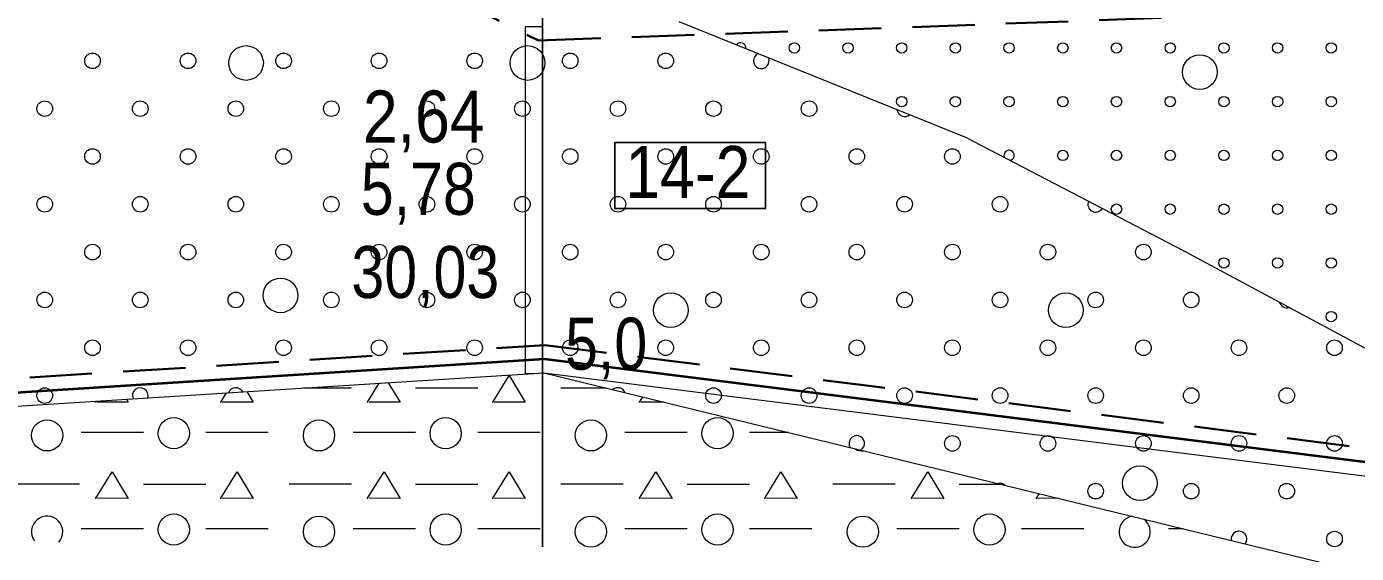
# Model space of a CAD drawing. Extents: x 640104 to 640970, y 6442278 to 6442689.
# Drawn here: x 640620 to 640696.8, y 6442553.6 to 6442583.9 of the extents above; entities that cross this region are included whole.
import ezdxf
from ezdxf.enums import TextEntityAlignment as Align

# ---------------------------------------------------------------- set-up
doc = ezdxf.new("R2010")
doc.units = 0
doc.header["$LTSCALE"] = 1.2
doc.linetypes.add('MEDIUM_DASHED', pattern=[4.5, 3, -1.5])
for name, color, linetype, lineweight in [('31', 7, 'Continuous', 13), ('32', 7, 'Continuous', 25), ('33', 7, 'Continuous', 13), ('35', 7, 'Continuous', 35), ('42', 7, 'Continuous', 13), ('43', 7, 'Continuous', 13), ('46', 7, 'Continuous', 13), ('47', 7, 'Continuous', 13)]:
    doc.layers.add(name, color=color, linetype=linetype, lineweight=lineweight)

msp = doc.modelspace()

# ---------------------------------------------------------------- linework, layer by layer
at = {"layer": '31'}
for points in [[(640657.64, 6442584.24), (640674.2, 6442577.56), (640686.8, 6442571.01), (640698.09, 6442564.96), (640704.51, 6442561.06), (640714.77, 6442554.82), (640726.06, 6442549.09), (640743.8, 6442541.09)], [(640553.71, 6442558.56), (640570.07, 6442558.94), (640649.85, 6442563.98), (640763.79, 6442536.22), (640808.67, 6442524.48), (640822.17, 6442520.94), (640837.77, 6442517.67), (640873.2, 6442509.45), (640884.27, 6442508.94), (640895.27, 6442508.94), (640947.47, 6442510.44), (640955.05, 6442510.44)]]:
    msp.add_lwpolyline(points, dxfattribs=at)
at = {"layer": '32'}
msp.add_line((640649.77, 6442613.94), (640649.77, 6442553.94), dxfattribs=at)
at = {"layer": '33'}
msp.add_lwpolyline([(640648.77, 6442583.94), (640648.77, 6442563.94), (640649.27, 6442563.94), (640649.77, 6442563.97), (640649.77, 6442563.98), (640649.77, 6442583.94), (640649.72, 6442583.94)], close=True, dxfattribs=at)
at = {"layer": '33', "lineweight": 25}
msp.add_lwpolyline([(640653.94, 6442577.26), (640662.65, 6442577.26), (640662.65, 6442573.46), (640653.94, 6442573.46)], close=True, dxfattribs=at)
at = {"layer": '35', "linetype": 'MEDIUM_DASHED'}
msp.add_line((640571.67, 6442560.65), (640649.9, 6442565.58), dxfattribs=at)
at = {"layer": '35', "lineweight": 40}
msp.add_line((640570.87, 6442559.79), (640649.88, 6442564.78), dxfattribs=at)
at = {"layer": '35', "linetype": 'MEDIUM_DASHED'}
for points in [[(640571.67, 6442622.27), (640649.54, 6442583.14), (640758.17, 6442587.08)], [(640649.9, 6442565.58), (640761.11, 6442551.63), (640823.77, 6442547.45)]]:
    msp.add_lwpolyline(points, dxfattribs=at)
at = {"layer": '35', "lineweight": 40}
msp.add_lwpolyline([(640649.88, 6442564.78), (640761.03, 6442550.84), (640822.97, 6442546.7)], dxfattribs=at)
at = {"layer": '35', "lineweight": 13}
msp.add_lwpolyline([(640649.85, 6442563.98), (640760.96, 6442550.04), (640822.17, 6442545.95)], dxfattribs=at)
at = {"layer": '42'}
for centre in [(640623.796, 6442581.971), (640629.311, 6442581.971), (640634.827, 6442581.971), (640640.342, 6442581.971), (640645.858, 6442581.971), (640651.373, 6442581.971), (640656.888, 6442581.971), (640621.038, 6442579.213), (640626.553, 6442579.213), (640632.069, 6442579.213), (640637.584, 6442579.213), (640643.1, 6442579.213), (640648.615, 6442579.213), (640654.131, 6442579.213), (640659.646, 6442579.213), (640665.162, 6442579.213), (640623.796, 6442576.456), (640629.311, 6442576.456), (640634.827, 6442576.456), (640640.342, 6442576.456), (640645.858, 6442576.456), (640651.373, 6442576.456), (640656.888, 6442576.456), (640662.404, 6442576.456), (640667.919, 6442576.456), (640673.435, 6442576.456), (640621.038, 6442573.698), (640626.553, 6442573.698), (640632.069, 6442573.698), (640637.584, 6442573.698), (640643.1, 6442573.698), (640648.615, 6442573.698), (640654.131, 6442573.698), (640659.646, 6442573.698), (640665.162, 6442573.698), (640670.677, 6442573.698), (640676.192, 6442573.698), (640623.796, 6442570.94), (640629.311, 6442570.94), (640634.827, 6442570.94), (640640.342, 6442570.94), (640645.858, 6442570.94), (640651.373, 6442570.94), (640656.888, 6442570.94), (640662.404, 6442570.94), (640667.919, 6442570.94), (640673.435, 6442570.94), (640678.95, 6442570.94), (640684.466, 6442570.94), (640621.038, 6442568.182), (640626.553, 6442568.182), (640632.069, 6442568.182), (640637.584, 6442568.182), (640643.1, 6442568.182), (640648.615, 6442568.182), (640654.131, 6442568.182), (640659.646, 6442568.182), (640665.162, 6442568.182), (640670.677, 6442568.182), (640676.192, 6442568.182), (640681.708, 6442568.182), (640687.223, 6442568.182), (640623.796, 6442565.425), (640629.311, 6442565.425), (640634.827, 6442565.425), (640640.342, 6442565.425), (640645.858, 6442565.425), (640651.373, 6442565.425), (640656.888, 6442565.425), (640662.404, 6442565.425), (640667.919, 6442565.425), (640673.435, 6442565.425), (640678.95, 6442565.425), (640684.466, 6442565.425), (640689.981, 6442565.425), (640695.496, 6442565.425), (640621.038, 6442562.667), (640659.646, 6442562.667), (640665.162, 6442562.667), (640670.677, 6442562.667), (640676.192, 6442562.667), (640681.708, 6442562.667), (640687.223, 6442562.667), (640692.739, 6442562.667), (640673.435, 6442559.909), (640678.95, 6442559.909), (640684.466, 6442559.909), (640689.981, 6442559.909), (640695.496, 6442559.909), (640681.708, 6442557.152), (640687.223, 6442557.152), (640692.739, 6442557.152), (640695.496, 6442554.394)]:
    msp.add_circle(centre, 0.45, dxfattribs=at)
for centre, start, end in [((640662.404, 6442581.971), 112.30663, 23.74435), ((640670.677, 6442579.213), 186.74405, 309.30693), ((640681.708, 6442573.698), 156.99398, 328.10403), ((640692.739, 6442568.182), 195.64186, 287.95488), ((640626.553, 6442562.667), 342.85116, 204.37372), ((640632.069, 6442562.667), 28.30655, 158.91833), ((640654.131, 6442562.667), 21.7371, 130.88036), ((640667.919, 6442559.909), 300.36297, 212.25448), ((640676.192, 6442557.152), 48.43112, 104.18634), ((640689.981, 6442554.394), 321.82605, 190.79141)]:
    msp.add_arc(centre, 0.45, start, end, dxfattribs=at)
at = {"layer": '43'}
for centre in [(640664.311, 6442582.718), (640667.411, 6442582.718), (640670.511, 6442582.718), (640673.611, 6442582.718), (640676.711, 6442582.718), (640679.811, 6442582.718), (640682.911, 6442582.718), (640686.011, 6442582.718), (640689.111, 6442582.718), (640692.211, 6442582.718), (640695.311, 6442582.718), (640670.511, 6442579.618), (640673.611, 6442579.618), (640676.711, 6442579.618), (640679.811, 6442579.618), (640682.911, 6442579.618), (640686.011, 6442579.618), (640689.111, 6442579.618), (640692.211, 6442579.618), (640695.311, 6442579.618), (640679.811, 6442576.518), (640682.911, 6442576.518), (640686.011, 6442576.518), (640689.111, 6442576.518), (640692.211, 6442576.518), (640695.311, 6442576.518), (640682.911, 6442573.418), (640686.011, 6442573.418), (640689.111, 6442573.418), (640692.211, 6442573.418), (640695.311, 6442573.418), (640689.111, 6442570.318), (640692.211, 6442570.318), (640695.311, 6442570.318), (640695.311, 6442567.218)]:
    msp.add_circle(centre, 0.3, dxfattribs=at)
for centre, start, end in [((640661.211, 6442582.718), 352.57349, 143.47749), ((640676.711, 6442576.518), 281.14874, 203.94927)]:
    msp.add_arc(centre, 0.3, start, end, dxfattribs=at)
at = {"layer": '46'}
for p, q in [((640638.74, 6442563.1), (640635.97, 6442563.1)), ((640646.04, 6442563.1), (640642.44, 6442563.1)), ((640653.45, 6442563.1), (640650.84, 6442563.1)), ((640656.8, 6442562.29), (640655.45, 6442562.29)), ((640626.74, 6442560.54), (640623.14, 6442560.54)), ((640633.94, 6442560.54), (640630.34, 6442560.54)), ((640642.44, 6442560.54), (640638.84, 6442560.54)), ((640649.64, 6442560.54), (640646.04, 6442560.54)), ((640658.13, 6442560.54), (640654.53, 6442560.54)), ((640663.97, 6442560.54), (640661.73, 6442560.54)), ((640623.05, 6442557.55), (640619.45, 6442557.55)), ((640630.34, 6442557.54), (640626.74, 6442557.54)), ((640638.74, 6442557.55), (640635.14, 6442557.55)), ((640646.04, 6442557.54), (640642.44, 6442557.54)), ((640654.44, 6442557.55), (640650.84, 6442557.55)), ((640661.73, 6442557.54), (640658.13, 6442557.54)), ((640670.13, 6442557.55), (640666.53, 6442557.55)), ((640676.27, 6442557.54), (640673.83, 6442557.54)), ((640679.59, 6442556.73), (640678.37, 6442556.74)), ((640626.74, 6442554.99), (640623.14, 6442554.99)), ((640633.94, 6442554.98), (640630.34, 6442554.98)), ((640642.44, 6442554.99), (640638.84, 6442554.99)), ((640649.64, 6442554.98), (640646.04, 6442554.98)), ((640658.13, 6442554.99), (640654.53, 6442554.99)), ((640665.33, 6442554.98), (640661.73, 6442554.98)), ((640673.83, 6442554.99), (640670.23, 6442554.99)), ((640681.03, 6442554.98), (640677.43, 6442554.98)), ((640686.75, 6442554.99), (640685.92, 6442554.99))]:
    msp.add_line(p, q, dxfattribs=at)
for points in [[(640646.9, 6442562.27), (640646.9, 6442562.29), (640647.85, 6442563.82), (640648.78, 6442562.28), (640646.98, 6442562.29)], [(640631.2, 6442562.27), (640631.2, 6442562.29), (640631.53, 6442562.82)], [(640632.71, 6442562.9), (640633.08, 6442562.28), (640631.28, 6442562.29)], [(640639.67, 6442562.27), (640639.68, 6442562.29), (640640.35, 6442563.38)], [(640640.87, 6442563.41), (640641.56, 6442562.28), (640639.76, 6442562.29)], [(640623.98, 6442562.27), (640623.98, 6442562.29), (640624.02, 6442562.35)], [(640625.76, 6442562.46), (640625.86, 6442562.28), (640624.06, 6442562.29)], [(640655.37, 6442562.27), (640655.37, 6442562.29), (640655.56, 6442562.59)], [(640623.98, 6442556.72), (640623.98, 6442556.74), (640624.93, 6442558.27), (640625.86, 6442556.73), (640624.06, 6442556.74)], [(640631.2, 6442556.72), (640631.2, 6442556.74), (640632.15, 6442558.27), (640633.08, 6442556.73), (640631.28, 6442556.74)], [(640639.67, 6442556.72), (640639.68, 6442556.74), (640640.63, 6442558.27), (640641.56, 6442556.73), (640639.76, 6442556.74)], [(640646.9, 6442556.72), (640646.9, 6442556.74), (640647.85, 6442558.27), (640648.78, 6442556.73), (640646.98, 6442556.74)], [(640655.37, 6442556.72), (640655.37, 6442556.74), (640656.32, 6442558.27), (640657.25, 6442556.73), (640655.45, 6442556.74)], [(640662.59, 6442556.72), (640662.6, 6442556.74), (640663.54, 6442558.27), (640664.47, 6442556.73), (640662.67, 6442556.74)], [(640671.07, 6442556.72), (640671.07, 6442556.74), (640672.02, 6442558.27), (640672.95, 6442556.73), (640671.15, 6442556.74)], [(640678.29, 6442556.72), (640678.29, 6442556.74), (640678.46, 6442557.01)]]:
    msp.add_lwpolyline(points, dxfattribs=at)
for centre in [(640621.176, 6442560.37), (640628.49, 6442560.492), (640636.872, 6442560.37), (640644.185, 6442560.492), (640652.567, 6442560.37), (640659.88, 6442560.492), (640628.49, 6442554.937), (640644.185, 6442554.937), (640659.88, 6442554.937), (640675.575, 6442554.937), (640636.872, 6442554.815), (640652.567, 6442554.815), (640668.262, 6442554.815)]:
    msp.add_circle(centre, 0.9, dxfattribs=at)
for centre, start, end in [((640668.262, 6442560.37), 237.45167, 275.16579), ((640621.176, 6442554.815), 318.21764, 215.75678), ((640683.957, 6442554.815), 99.05909, 53.55837)]:
    msp.add_arc(centre, 0.9, start, end, dxfattribs=at)
at = {"layer": '47'}
for centre in [(640632.658, 6442581.847), (640648.909, 6442581.847), (640687.718, 6442581.326), (640634.653, 6442568.446), (640657.177, 6442567.591), (640679.986, 6442567.591), (640684.263, 6442557.612)]:
    msp.add_circle(centre, 1, dxfattribs=at)

# ---------------------------------------------------------------- texts
at = {"layer": '32', "width": 0.85}
msp.add_text('5,0', height=3, dxfattribs=at).set_placement((640653.45, 6442564.16), align=Align.CENTER)
at = {"layer": '33'}
for s, width, p in [('2,64', 0.9, (640642.92, 6442577.26)), ('14-2', 0.9, (640658.165, 6442574.06)), ('5,78', 0.85, (640642.605, 6442573.09)), ('30,03', 0.85, (640643.01, 6442568.29))]:
    msp.add_text(s, height=3, dxfattribs=dict(at, width=width)).set_placement(p, align=Align.CENTER)

doc.saveas('drawing.dxf')
